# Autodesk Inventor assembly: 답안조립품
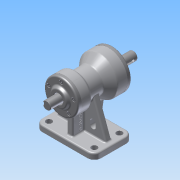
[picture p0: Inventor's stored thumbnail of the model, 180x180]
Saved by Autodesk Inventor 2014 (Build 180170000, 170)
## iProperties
Created: 2015-08
Part Number: 답안조립품
Document SubType Name: Assembly
Designer: study
Author: study
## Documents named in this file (10)
- C:\Users\study\Desktop\450805V1031\답안조립품.iam
- C:\Users\study\Desktop\450805V1031\1-본체.ipt
- C:\Users\study\Desktop\450805V1031\베어링 6205.ipt
- C:\Users\study\Desktop\450805V1031\베어링 6203.ipt
- C:\Users\study\Desktop\450805V1031\축.ipt
- C:\Users\study\Desktop\450805V1031\뒤커버.ipt
- C:\Users\study\Desktop\450805V1031\앞커버.ipt
- C:\Users\study\Desktop\450805V1031\오일실 .ipt
- 오일실 .ipt
- C:\Users\study\Desktop\450805V1031\M4x0.5.ipt
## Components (11 placed, 2 different names)
1. 1-본체:1
2. M4x0.5:2
3. M4x0.5:3
4. M4x0.5:4
5. M4x0.5:5
6. M4x0.5:6
7. M4x0.5:1
8. M4x0.5:7
9. M4x0.5:8
10. M4x0.5:9
11. M4x0.5:10
